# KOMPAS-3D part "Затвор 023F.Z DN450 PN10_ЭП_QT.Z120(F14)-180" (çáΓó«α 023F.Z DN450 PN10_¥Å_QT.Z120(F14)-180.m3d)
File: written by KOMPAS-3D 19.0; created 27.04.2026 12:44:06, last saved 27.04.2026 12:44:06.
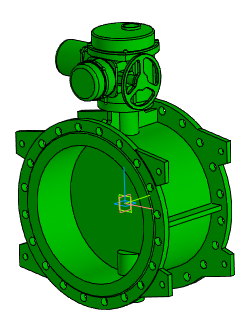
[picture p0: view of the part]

Document properties: Полное имя файла: Затвор 023F.Z DN450 PN10 +  электропривод QT.Z120(F14)-180.a3d

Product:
- Part/product: Затвор 023F.Z DN450 PN10_ЭП_QT.Z120(F14)-180
    Масса: 256.782
  - Body: Тело 1
      Масса: 257.294

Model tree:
1. Операция без истории:1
